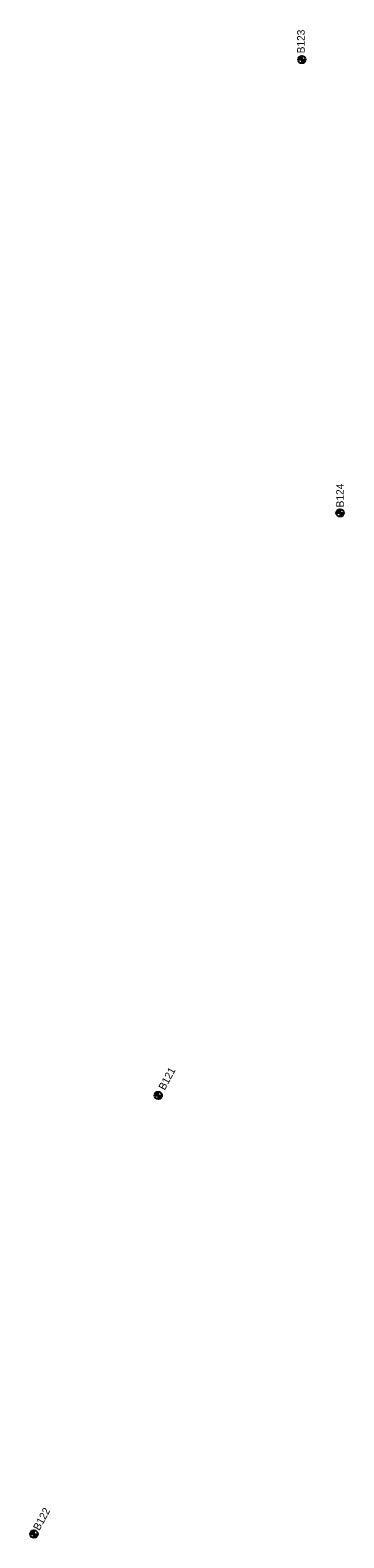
# Model space of a CAD drawing. Extents: x 311409 to 379449, y 121539 to 224848.
# Drawn here: x 356213 to 356628, y 195167 to 197160 of the extents above; entities that cross this region are included whole.
import ezdxf

# ---------------------------------------------------------------- set-up
doc = ezdxf.new("R2010")
doc.units = 0
for name, color, linetype in [('E_SOIL_BORE1 [KAPUR_CADDS_LEVELS]', 7, 'Continuous'), ('E_SOIL_BORE2 [KAPUR_CADDS_LEVELS]', 7, 'Continuous'), ('P_MARK', 7, 'Continuous')]:
    doc.layers.add(name, color=color, linetype=linetype)

msp = doc.modelspace()

# ---------------------------------------------------------------- linework, layer by layer
at = {"layer": 'P_MARK'}
for p, q in [((356572.3, 197126), (356572.3, 197116)), ((356567.3, 197121), (356577.3, 197121)), ((356617.9, 196521.9), (356627.9, 196521.9)), ((356622.9, 196526.9), (356622.9, 196516.9)), ((356377.4, 195752), (356387.4, 195752)), ((356382.4, 195757), (356382.4, 195747)), ((356218, 195177.4), (356218, 195167.4)), ((356213, 195172.4), (356223, 195172.4))]:
    msp.add_line(p, q, dxfattribs=at)
for centre in [(356572.3, 197121), (356622.9, 196521.9), (356382.4, 195752), (356218, 195172.4)]:
    msp.add_circle(centre, 5, dxfattribs=at)
for centre, radius, start, end in [((356572.3, 197121), 4.5, 89.9869, 179.9869), ((356572.3, 197121), 4, 89.9869, 179.9869), ((356572.3, 197121), 3.5, 89.9869, 179.9869), ((356572.3, 197121), 3, 89.9869, 179.9869), ((356572.3, 197121), 2.5, 89.9869, 179.9869), ((356572.3, 197121), 2, 89.9869, 179.9869), ((356572.3, 197121), 1.5, 89.9869, 179.9869), ((356572.3, 197121), 1, 89.9869, 179.9869), ((356572.3, 197121), 0.5, 89.9869, 179.9869), ((356572.3, 197121), 4.5, 269.9869, 359.9869), ((356572.3, 197121), 4, 269.9869, 359.9869), ((356572.3, 197121), 3.5, 269.9869, 359.9869), ((356572.3, 197121), 3, 269.9869, 359.9869), ((356572.3, 197121), 2.5, 269.9869, 359.9869), ((356572.3, 197121), 2, 269.9869, 359.9869), ((356572.3, 197121), 1.5, 269.9869, 359.9869), ((356572.3, 197121), 1, 269.9869, 359.9869), ((356572.3, 197121), 0.5, 269.9869, 359.9869), ((356622.9, 196521.9), 4.5, 89.9869, 179.9869), ((356622.9, 196521.9), 4, 89.9869, 179.9869), ((356622.9, 196521.9), 3.5, 89.9869, 179.9869), ((356622.9, 196521.9), 3, 89.9869, 179.9869), ((356622.9, 196521.9), 2.5, 89.9869, 179.9869), ((356622.9, 196521.9), 2, 89.9869, 179.9869), ((356622.9, 196521.9), 1.5, 89.9869, 179.9869), ((356622.9, 196521.9), 1, 89.9869, 179.9869), ((356622.9, 196521.9), 0.5, 89.9869, 179.9869), ((356622.9, 196521.9), 4.5, 269.9869, 359.9869), ((356622.9, 196521.9), 4, 269.9869, 359.9869), ((356622.9, 196521.9), 3.5, 269.9869, 359.9869), ((356622.9, 196521.9), 3, 269.9869, 359.9869), ((356622.9, 196521.9), 2.5, 269.9869, 359.9869), ((356622.9, 196521.9), 2, 269.9869, 359.9869), ((356622.9, 196521.9), 1.5, 269.9869, 359.9869), ((356622.9, 196521.9), 1, 269.9869, 359.9869), ((356622.9, 196521.9), 0.5, 269.9869, 359.9869), ((356382.4, 195752), 4.5, 89.9869, 179.9869), ((356382.4, 195752), 4, 89.9869, 179.9869), ((356382.4, 195752), 3.5, 89.9869, 179.9869), ((356382.4, 195752), 3, 89.9869, 179.9869), ((356382.4, 195752), 2.5, 89.9869, 179.9869), ((356382.4, 195752), 2, 89.9869, 179.9869), ((356382.4, 195752), 1.5, 89.9869, 179.9869), ((356382.4, 195752), 1, 89.9869, 179.9869), ((356382.4, 195752), 0.5, 89.9869, 179.9869), ((356382.4, 195752), 4.5, 269.9869, 359.9869), ((356382.4, 195752), 4, 269.9869, 359.9869), ((356382.4, 195752), 3.5, 269.9869, 359.9869), ((356382.4, 195752), 3, 269.9869, 359.9869), ((356382.4, 195752), 2.5, 269.9869, 359.9869), ((356382.4, 195752), 2, 269.9869, 359.9869), ((356382.4, 195752), 1.5, 269.9869, 359.9869), ((356382.4, 195752), 1, 269.9869, 359.9869), ((356382.4, 195752), 0.5, 269.9869, 359.9869), ((356218, 195172.4), 4.5, 89.9869, 179.9869), ((356218, 195172.4), 4, 89.9869, 179.9869), ((356218, 195172.4), 3.5, 89.9869, 179.9869), ((356218, 195172.4), 3, 89.9869, 179.9869), ((356218, 195172.4), 2.5, 89.9869, 179.9869), ((356218, 195172.4), 2, 89.9869, 179.9869), ((356218, 195172.4), 1.5, 89.9869, 179.9869), ((356218, 195172.4), 1, 89.9869, 179.9869), ((356218, 195172.4), 0.5, 89.9869, 179.9869), ((356218, 195172.4), 4.5, 269.9869, 359.9869), ((356218, 195172.4), 4, 269.9869, 359.9869), ((356218, 195172.4), 3.5, 269.9869, 359.9869), ((356218, 195172.4), 3, 269.9869, 359.9869), ((356218, 195172.4), 2.5, 269.9869, 359.9869), ((356218, 195172.4), 2, 269.9869, 359.9869), ((356218, 195172.4), 1.5, 269.9869, 359.9869), ((356218, 195172.4), 1, 269.9869, 359.9869), ((356218, 195172.4), 0.5, 269.9869, 359.9869)]:
    msp.add_arc(centre, radius, start, end, dxfattribs=at)

# ---------------------------------------------------------------- texts
at = {"layer": 'E_SOIL_BORE1 [KAPUR_CADDS_LEVELS]'}
for s, rotation, p in [('B124', 89.9869, (356627.8, 196529.2)), ('B121', 61.5935, (356390.9, 195758.2)), ('B122', 61.5935, (356225.2, 195176.3))]:
    msp.add_text(s, height=10, rotation=rotation, dxfattribs=at).set_placement(p)
at = {"layer": 'E_SOIL_BORE2 [KAPUR_CADDS_LEVELS]'}
msp.add_text('B123', height=10, rotation=89.9869, dxfattribs=at).set_placement((356576.1, 197129.2))

doc.saveas('drawing.dxf')
